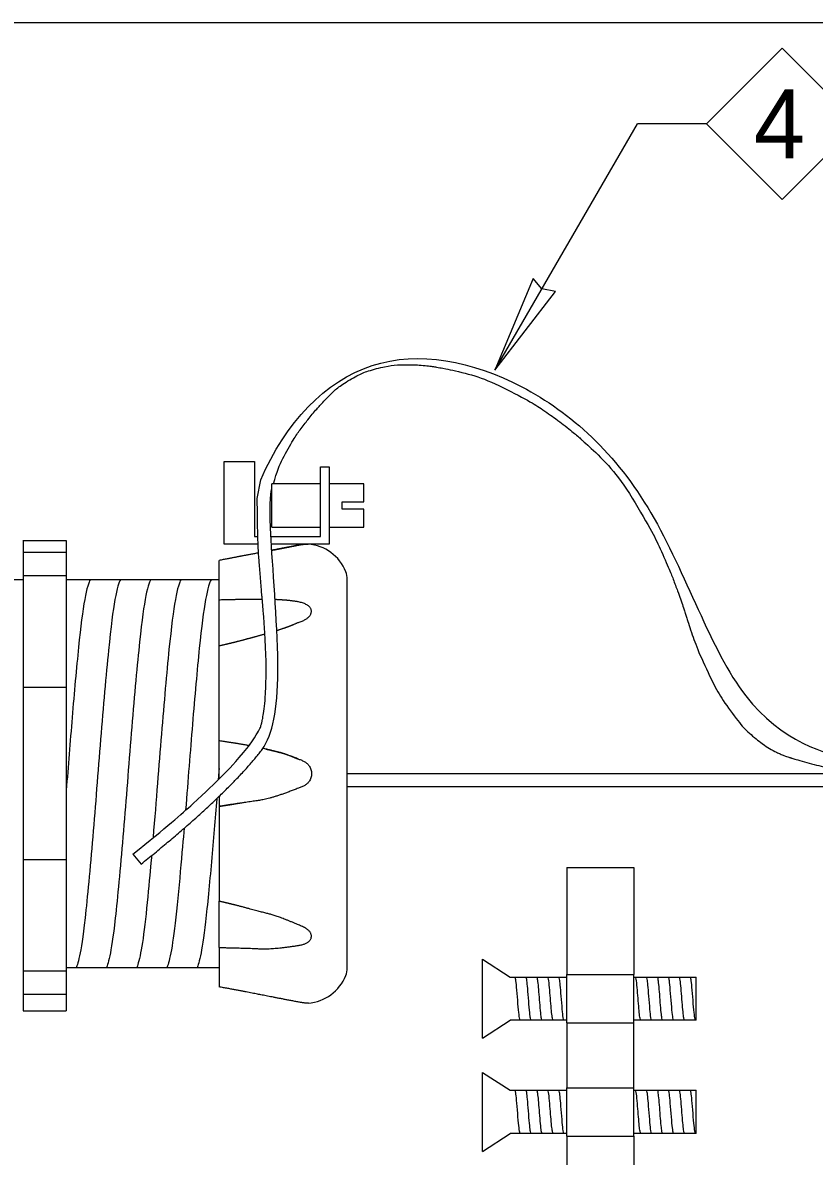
# Model space of a CAD drawing. Extents: x 99862 to 103680, y 99470 to 102076.
# Drawn here: x 101298.9 to 101482.3, y 100237.8 to 100500.5 of the extents above; entities that cross this region are included whole.
import ezdxf

# ---------------------------------------------------------------- set-up
doc = ezdxf.new("R2010")
doc.units = 0
for name, color, linetype in [('Level 1', 7, 'Continuous'), ('Level 10', 7, 'Continuous'), ('Level 15', 7, 'Continuous'), ('Level 20', 7, 'Continuous'), ('Level 4', 7, 'Continuous'), ('Level 5', 7, 'Continuous'), ('Level 7', 7, 'Continuous'), ('Level 8', 7, 'Continuous'), ('Level 9', 7, 'Continuous')]:
    doc.layers.add(name, color=color, linetype=linetype)

msp = doc.modelspace()

# ---------------------------------------------------------------- linework, layer by layer
at = {"layer": 'Level 1'}
msp.add_line((102062.21, 100500.54), (101248.49, 100500.54), dxfattribs=at)
at = {"layer": 'Level 10'}
for p, q in [((101405.4, 100265.15), (101405.4, 100283.46)), ((101405.4, 100283.46), (101411.85, 100279.31)), ((101411.85, 100279.31), (101424.99, 100279.31)), ((101440.46, 100279.31), (101454.9, 100279.31)), ((101454.9, 100269.31), (101454.9, 100279.31)), ((101405.4, 100265.15), (101411.85, 100269.31)), ((101424.99, 100269.31), (101411.85, 100269.31)), ((101454.9, 100269.31), (101440.46, 100269.31)), ((101405.4, 100238.92), (101405.4, 100257.23)), ((101405.4, 100257.23), (101411.85, 100253.07)), ((101411.85, 100253.07), (101424.99, 100253.07)), ((101440.46, 100253.07), (101454.9, 100253.07)), ((101454.9, 100243.07), (101454.9, 100253.07)), ((101405.4, 100238.92), (101411.85, 100243.07)), ((101424.99, 100243.07), (101411.85, 100243.07)), ((101454.9, 100243.07), (101440.46, 100243.07))]:
    msp.add_line(p, q, dxfattribs=at)
for points, degree in [([(101314.55, 100371.41), (101314.24, 100370.92), (101313.27, 100367.9), (101311.88, 100356.86), (101310.34, 100339.4), (101309.46, 100328.19), (101309.01, 100322.59)], 3), ([(101321.55, 100371.41), (101321.24, 100370.92), (101320.27, 100367.9), (101318.88, 100356.86), (101316.92, 100334.58), (101315.18, 100311.37), (101313.22, 100290.82), (101312.08, 100283.49), (101311.37, 100281.54), (101311.32, 100281.41)], 3), ([(101328.55, 100371.41), (101328.24, 100370.92), (101327.27, 100367.9), (101325.88, 100356.86), (101323.92, 100334.58), (101322.18, 100311.37), (101320.22, 100290.82), (101319.08, 100283.49), (101318.37, 100281.54), (101318.32, 100281.41)], 3), ([(101335.55, 100371.41), (101335.24, 100370.92), (101334.27, 100367.9), (101332.88, 100356.86), (101331.04, 100336.01), (101329.86, 100320.5), (101329.12, 100311.63)], 3), ([(101342.55, 100371.41), (101342.24, 100370.92), (101341.27, 100367.9), (101339.88, 100356.86), (101338.22, 100338.01), (101337.21, 100325.07), (101336.65, 100318.03)], 3), ([(101344.41, 100327.63), (101344.34, 100326.76), (101344.28, 100325.9), (101344.21, 100325.03)], 2), ([(101343.86, 100320.66), (101343.49, 100316.02), (101342.68, 100306.14), (101341.22, 100290.82), (101340.08, 100283.49), (101339.37, 100281.54), (101339.32, 100281.41)], 3), ([(101336.3, 100313.8), (101336.11, 100311.54), (101335.49, 100304.19), (101334.22, 100290.82), (101333.08, 100283.49), (101332.37, 100281.54), (101332.32, 100281.41)], 3), ([(101328.76, 100307.46), (101328.76, 100307.38), (101328.31, 100302.31), (101327.22, 100290.82), (101326.08, 100283.49), (101325.37, 100281.54), (101325.32, 100281.41)], 3), ([(101414.15, 100269.31), (101414.09, 100269.39), (101413.95, 100269.95), (101413.72, 100272.16), (101413.46, 100275.69), (101413.22, 100278.35), (101413.06, 100279.14), (101413.01, 100279.29), (101413.01, 100279.31)], 3), ([(101416.68, 100269.31), (101416.64, 100269.36), (101416.56, 100269.63), (101416.38, 100270.84), (101416.14, 100273.72), (101415.9, 100276.86), (101415.7, 100278.65), (101415.6, 100279.17), (101415.54, 100279.31)], 3), ([(101419.22, 100269.31), (101419.21, 100269.32), (101419.1, 100269.55), (101418.92, 100270.82), (101418.7, 100273.45), (101418.51, 100275.92), (101418.32, 100278.11), (101418.17, 100279.07), (101418.09, 100279.29), (101418.08, 100279.31)], 3), ([(101421.76, 100269.31), (101421.72, 100269.36), (101421.61, 100269.7), (101421.46, 100270.92), (101421.27, 100273.13), (101421.07, 100275.64), (101420.85, 100278.18), (101420.7, 100279.11), (101420.62, 100279.31)], 3), ([(101424.29, 100269.31), (101424.26, 100269.36), (101424.13, 100269.78), (101423.92, 100271.62), (101423.66, 100275.01), (101423.44, 100277.66), (101423.27, 100278.93), (101423.19, 100279.23), (101423.16, 100279.31)], 3), ([(101442.06, 100269.31), (101442.03, 100269.36), (101441.92, 100269.7), (101441.76, 100270.92), (101441.57, 100273.13), (101441.38, 100275.64), (101441.15, 100278.18), (101441, 100279.11), (101440.92, 100279.31)], 3), ([(101444.6, 100269.31), (101444.57, 100269.36), (101444.43, 100269.78), (101444.23, 100271.62), (101443.96, 100275.01), (101443.75, 100277.66), (101443.57, 100278.93), (101443.49, 100279.23), (101443.46, 100279.31)], 3), ([(101447.14, 100269.31), (101447.1, 100269.36), (101447, 100269.7), (101446.84, 100270.93), (101446.62, 100273.4), (101446.43, 100275.98), (101446.21, 100278.26), (101446.09, 100279.08), (101446.01, 100279.29), (101446, 100279.31)], 3), ([(101449.68, 100269.31), (101449.62, 100269.4), (101449.49, 100269.97), (101449.26, 100272.16), (101448.99, 100275.69), (101448.75, 100278.35), (101448.6, 100279.15), (101448.55, 100279.29), (101448.54, 100279.31)], 3), ([(101452.21, 100269.31), (101452.18, 100269.36), (101452.07, 100269.7), (101451.89, 100271.12), (101451.7, 100273.45), (101451.48, 100276.22), (101451.28, 100278.42), (101451.13, 100279.17), (101451.08, 100279.31)], 3), ([(101454.76, 100269.31), (101454.7, 100269.39), (101454.56, 100269.95), (101454.34, 100272.16), (101454.07, 100275.69), (101453.83, 100278.35), (101453.68, 100279.14), (101453.62, 100279.29), (101453.62, 100279.31)], 3), ([(101414.15, 100243.07), (101414.09, 100243.16), (101413.95, 100243.72), (101413.72, 100245.92), (101413.46, 100249.46), (101413.22, 100252.12), (101413.06, 100252.91), (101413.01, 100253.06), (101413.01, 100253.07)], 3), ([(101416.68, 100243.07), (101416.64, 100243.13), (101416.56, 100243.39), (101416.38, 100244.61), (101416.14, 100247.49), (101415.9, 100250.63), (101415.7, 100252.42), (101415.6, 100252.93), (101415.54, 100253.07)], 3), ([(101419.22, 100243.07), (101419.21, 100243.09), (101419.1, 100243.31), (101418.92, 100244.59), (101418.7, 100247.22), (101418.51, 100249.68), (101418.32, 100251.87), (101418.17, 100252.84), (101418.09, 100253.06), (101418.08, 100253.07)], 3), ([(101421.76, 100243.07), (101421.72, 100243.13), (101421.61, 100243.46), (101421.46, 100244.69), (101421.27, 100246.89), (101421.07, 100249.41), (101420.85, 100251.94), (101420.7, 100252.87), (101420.62, 100253.07)], 3), ([(101424.29, 100243.07), (101424.26, 100243.13), (101424.13, 100243.54), (101423.92, 100245.38), (101423.66, 100248.77), (101423.44, 100251.42), (101423.27, 100252.69), (101423.19, 100253), (101423.16, 100253.07)], 3), ([(101442.06, 100243.07), (101442.03, 100243.13), (101441.92, 100243.46), (101441.76, 100244.69), (101441.57, 100246.89), (101441.38, 100249.41), (101441.15, 100251.94), (101441, 100252.87), (101440.92, 100253.07)], 3), ([(101444.6, 100243.07), (101444.57, 100243.13), (101444.43, 100243.54), (101444.23, 100245.38), (101443.96, 100248.77), (101443.75, 100251.42), (101443.57, 100252.69), (101443.49, 100253), (101443.46, 100253.07)], 3), ([(101447.14, 100243.07), (101447.1, 100243.13), (101447, 100243.46), (101446.84, 100244.69), (101446.62, 100247.17), (101446.43, 100249.75), (101446.21, 100252.03), (101446.09, 100252.84), (101446.01, 100253.06), (101446, 100253.07)], 3), ([(101449.68, 100243.07), (101449.62, 100243.17), (101449.49, 100243.73), (101449.26, 100245.92), (101448.99, 100249.46), (101448.75, 100252.12), (101448.6, 100252.91), (101448.55, 100253.06), (101448.54, 100253.07)], 3), ([(101452.21, 100243.07), (101452.18, 100243.13), (101452.07, 100243.47), (101451.89, 100244.88), (101451.7, 100247.22), (101451.48, 100249.99), (101451.28, 100252.19), (101451.13, 100252.94), (101451.08, 100253.07)], 3), ([(101454.76, 100243.07), (101454.7, 100243.16), (101454.56, 100243.72), (101454.34, 100245.92), (101454.07, 100249.46), (101453.83, 100252.12), (101453.68, 100252.91), (101453.62, 100253.06), (101453.62, 100253.07)], 3)]:
    msp.add_open_spline(points, degree=degree, dxfattribs=at)
at = {"layer": 'Level 15'}
for p in [(101408.32, 100419.97), (101457.3, 100477.1)]:
    msp.add_line(p, (101441.3, 100477.1), dxfattribs=at)
msp.add_lwpolyline([(101408.32, 100419.97), (101422.32, 100438.25), (101419.21, 100438.83), (101417.15, 100441.24)], close=True, dxfattribs=at)
at = {"layer": 'Level 20'}
msp.add_lwpolyline([(101474.86, 100494.65), (101492.41, 100477.1), (101474.86, 100459.54), (101457.3, 100477.1)], close=True, dxfattribs=at)
at = {"layer": 'Level 4'}
for p, q in [((101298.92, 100380.54), (101309.01, 100380.54)), ((101299.01, 100380.54), (101299.01, 100271.47)), ((101309.01, 100380.54), (101309.01, 100271.47)), ((101309.01, 100377.71), (101299.01, 100377.71)), ((101309.01, 100372.3), (101299.01, 100372.3)), ((101295.35, 100371.47), (101299.01, 100371.47)), ((101309.01, 100371.47), (101344.41, 100371.47)), ((101309.01, 100346.47), (101299.01, 100346.47)), ((101309.01, 100306.47), (101299.01, 100306.47)), ((101309.01, 100280.65), (101299.01, 100280.65)), ((101344.41, 100281.47), (101308.98, 100281.47)), ((101309.01, 100275.24), (101299.01, 100275.24)), ((101299.01, 100271.47), (101309.01, 100271.47))]:
    msp.add_line(p, q, dxfattribs=at)
at = {"layer": 'Level 5'}
for p, q in [((101344.41, 100325.23), (101344.41, 100375.89)), ((101374.08, 100281.47), (101374.08, 100371.47)), ((101344.41, 100321.19), (101344.41, 100318.88)), ((101344.41, 100318.88), (101344.41, 100296.9)), ((101344.41, 100286.16), (101344.41, 100296.9)), ((101344.41, 100286.16), (101344.41, 100277.05))]:
    msp.add_line(p, q, dxfattribs=at)
for centre, radius, start, end in [((101364.41, 100369.67), 10, 21.1568, 86.3269), ((101369.08, 100371.47), 5, 0, 21.1568), ((101369.08, 100371.47), 5, 0, 21.1568), ((101369.08, 100281.47), 5, 338.8432, 0), ((101364.41, 100283.28), 10, 273.6858, 338.8432)]:
    msp.add_arc(centre, radius, start, end, dxfattribs=at)
for points in [[(101353.56, 100377.64), (101350.52, 100377.06), (101347.46, 100376.47), (101344.41, 100375.89)], [(101362.87, 100379.45), (101360.79, 100379.04), (101358.67, 100378.63), (101356.52, 100378.22)], [(101356.52, 100378.21), (101358.65, 100378.62), (101360.74, 100379.03), (101362.77, 100379.43)], [(101362.77, 100379.43), (101363.88, 100379.65), (101364.78, 100379.64), (101365.03, 100379.65)], [(101365.1, 100379.65), (101365.05, 100379.64), (101364.2, 100379.68), (101362.87, 100379.45)], [(101344.41, 100366.79), (101347.74, 100366.85), (101351.1, 100366.97), (101354.41, 100366.92)], [(101362.77, 100366.3), (101361.02, 100366.56), (101359.24, 100366.72), (101357.43, 100366.82)], [(101362.77, 100361.53), (101365.67, 100362.43), (101365.91, 100365.58), (101362.77, 100366.3)], [(101357.97, 100359.71), (101359.6, 100360.25), (101361.21, 100360.85), (101362.77, 100361.53)], [(101349.12, 100357.19), (101347.56, 100356.79), (101345.98, 100356.42), (101344.41, 100356.05)], [(101355.02, 100358.81), (101353.06, 100358.24), (101351.08, 100357.72), (101349.12, 100357.19)], [(101351.39, 100332.95), (101349.07, 100333.37), (101346.74, 100333.72), (101344.41, 100334.07)], [(101362.77, 100329.85), (101360.11, 100330.92), (101357.36, 100331.69), (101354.57, 100332.31)], [(101355.35, 100332.14), (101357.87, 100331.57), (101360.36, 100330.85), (101362.77, 100329.85)], [(101362.77, 100329.85), (101365.84, 100328.92), (101365.83, 100324.02), (101362.77, 100323.1)], [(101362.77, 100323.1), (101356.9, 100320.75), (101350.62, 100319.81), (101344.41, 100318.88)], [(101344.41, 100318.88), (101346.01, 100319.14), (101347.62, 100319.39), (101349.22, 100319.65)], [(101349.12, 100295.76), (101347.56, 100296.16), (101345.98, 100296.53), (101344.41, 100296.9)], [(101362.77, 100291.42), (101358.42, 100293.33), (101353.73, 100294.52), (101349.12, 100295.76)], [(101362.77, 100286.65), (101365.67, 100287.07), (101365.91, 100290.29), (101362.77, 100291.42)], [(101344.41, 100286.16), (101350.6, 100286.05), (101356.92, 100285.73), (101362.77, 100286.65)], [(101362.87, 100273.5), (101356.9, 100274.66), (101350.62, 100275.88), (101344.41, 100277.05)], [(101365.1, 100273.3), (101365.05, 100273.31), (101364.2, 100273.27), (101362.87, 100273.5)]]:
    msp.add_open_spline(points, degree=2, dxfattribs=at)
at = {"layer": 'Level 7'}
for p, q in [((101424.99, 100304.68), (101424.99, 100279.91)), ((101424.99, 100304.68), (101440.46, 100304.68)), ((101424.99, 100304.68), (101424.99, 100293.12)), ((101440.46, 100304.68), (101440.46, 100279.91)), ((101424.99, 100279.91), (101440.46, 100279.91)), ((101424.99, 100268.71), (101424.99, 100279.91)), ((101440.46, 100268.71), (101440.46, 100279.91)), ((101424.99, 100268.71), (101440.46, 100268.71)), ((101424.99, 100268.71), (101424.99, 100253.67)), ((101440.46, 100253.67), (101440.46, 100268.71)), ((101424.99, 100253.67), (101440.46, 100253.67)), ((101424.99, 100242.47), (101424.99, 100253.67)), ((101440.46, 100242.47), (101440.46, 100253.67)), ((101424.99, 100242.47), (101440.46, 100242.47)), ((101424.99, 100242.47), (101424.99, 100227.44)), ((101440.46, 100242.47), (101440.46, 100227.44))]:
    msp.add_line(p, q, dxfattribs=at)
at = {"layer": 'Level 8'}
for p, q in [((101345.61, 100379.65), (101345.61, 100398.81)), ((101345.61, 100398.81), (101352.6, 100398.81)), ((101352.6, 100398.81), (101352.6, 100381.44)), ((101367.87, 100397.61), (101369.95, 100397.61)), ((101367.87, 100381.44), (101367.87, 100397.61)), ((101369.95, 100397.61), (101369.95, 100379.65)), ((101356.62, 100383.63), (101356.62, 100393.63)), ((101367.87, 100393.63), (101356.62, 100393.63)), ((101377.94, 100393.63), (101369.95, 100393.63)), ((101377.94, 100389.51), (101377.94, 100393.63)), ((101372.94, 100389.51), (101377.94, 100389.51)), ((101372.94, 100387.75), (101372.94, 100389.51)), ((101377.94, 100387.75), (101372.94, 100387.75)), ((101377.94, 100383.63), (101377.94, 100387.75)), ((101356.62, 100383.63), (101367.87, 100383.63)), ((101369.95, 100383.63), (101377.94, 100383.63)), ((101352.6, 100381.44), (101353.39, 100381.44)), ((101356.32, 100381.44), (101367.87, 100381.44)), ((101353.44, 100379.65), (101345.61, 100379.65)), ((101369.95, 100379.65), (101356.43, 100379.65))]:
    msp.add_line(p, q, dxfattribs=at)
at = {"layer": 'Level 9'}
for p, q in [((101353.2, 100390.27), (101354.05, 100394.56)), ((101374.08, 100326.47), (101491.22, 100326.47)), ((101374.08, 100323.47), (101491.22, 100323.47)), ((101324.47, 100307.84), (101326.34, 100305.5))]:
    msp.add_line(p, q, dxfattribs=at)
for points, degree in [([(101354.05, 100394.56), (101359.84, 100407.91), (101378.24, 100427.09), (101415.54, 100419.63), (101446.81, 100391.19), (101463.97, 100337.01), (101485.2, 100330.82), (101491.22, 100329.81)], 3), ([(101357.03, 100393.63), (101357.78, 100396.5), (101359.02, 100399.44), (101361.82, 100404.23), (101363.05, 100406.03), (101365.17, 100408.77), (101365.92, 100409.69), (101367.12, 100411.08), (101367.74, 100411.77), (101368.49, 100412.59), (101368.88, 100413), (101369.04, 100413.17), (101369.15, 100413.29), (101369.21, 100413.35), (101370.95, 100415.16), (101372.75, 100416.6), (101376.61, 100418.9), (101378.66, 100419.77), (101383.1, 100420.94), (101385.49, 100421.25), (101389.34, 100421.27), (101390.67, 100421.21), (101392.73, 100421), (101393.78, 100420.86), (101394.85, 100420.69), (101395.57, 100420.56), (101395.93, 100420.49), (101402.24, 100419.23), (101407.93, 100417.21), (101416.13, 100412.91), (101418.81, 100411.27), (101422.75, 100408.48), (101424.05, 100407.5), (101425.98, 100405.94), (101426.94, 100405.15), (101428.05, 100404.18), (101428.53, 100403.76), (101428.84, 100403.47), (101429, 100403.33), (101434.12, 100398.68), (101438.56, 100393.11), (101444.41, 100383.12), (101446.23, 100379.52), (101448.75, 100373.71), (101449.55, 100371.7), (101450.71, 100368.59), (101451.27, 100367), (101451.91, 100365.11), (101452.22, 100364.16), (101452.38, 100363.68), (101452.44, 100363.47), (101452.49, 100363.33), (101452.51, 100363.26), (101453.99, 100358.58), (101455.57, 100354.42), (101459.01, 100347.03), (101460.85, 100343.79), (101464.87, 100338.23), (101467.04, 100335.9), (101470.58, 100333.14), (101471.81, 100332.34), (101473.71, 100331.34), (101474.36, 100331.04), (101475.35, 100330.64), (101475.84, 100330.45), (101476.43, 100330.26), (101476.72, 100330.17), (101476.87, 100330.12), (101476.94, 100330.1), (101476.98, 100330.09), (101477, 100330.08), (101481.74, 100328.7), (101486.08, 100327.67), (101490.44, 100326.9), (101490.83, 100326.83), (101491.22, 100326.77)], 3), ([(101354.4, 100332.06), (101356.8, 100335.74), (101359.23, 100346.33), (101355.74, 100386), (101356.33, 100391.05), (101356.62, 100392.56)], 3), ([(101351.24, 100332.73), (101353.49, 100336.11), (101353.93, 100337.02), (101354.2, 100337.86), (101354.25, 100338.02), (101354.28, 100338.17), (101354.29, 100338.2), (101354.3, 100338.25), (101354.32, 100338.33), (101354.36, 100338.51), (101354.48, 100339.11), (101354.59, 100339.69), (101354.97, 100342.14), (101355.17, 100344.52), (101355.34, 100350.05), (101355.3, 100353.2), (101355.05, 100358.49), (101354.94, 100360.35), (101354.72, 100363.28), (101354.64, 100364.28), (101354.51, 100365.81), (101354.46, 100366.34), (101354.37, 100367.36), (101354.33, 100367.87), (101353.95, 100372.33), (101353.68, 100375.78), (101353.45, 100379.2), (101353.42, 100379.69), (101353.2, 100390.27)], 3), ([(101324.47, 100307.84), (101332.4, 100314.21), (101338.79, 100319.76), (101345.9, 100326.67), (101347.84, 100328.72), (101351.24, 100332.73)], 3), ([(101326.34, 100305.5), (101346.13, 100321.39), (101354.4, 100332.06)], 2)]:
    msp.add_open_spline(points, degree=degree, dxfattribs=at)

# ---------------------------------------------------------------- texts
at = {"layer": 'Level 20'}
msp.add_text('4', height=16, dxfattribs=at).set_placement((101468.26, 100469.1))

doc.saveas('drawing.dxf')
